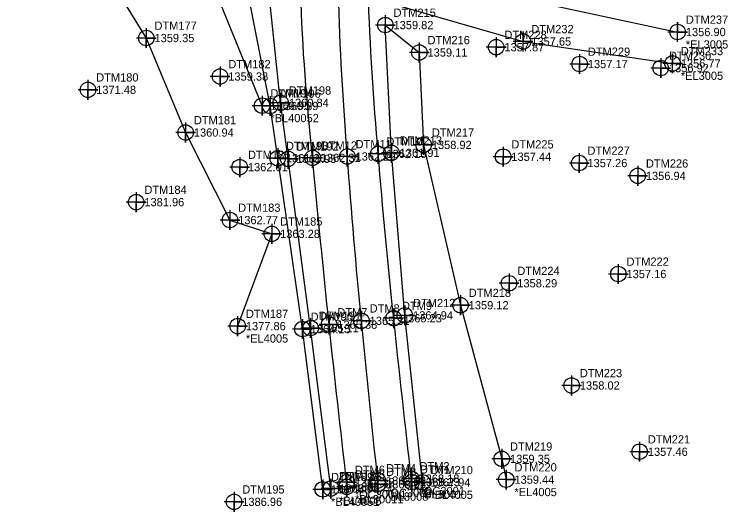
# Model space of a CAD drawing. Extents: x 1251905 to 1252853, y 859795 to 860170.
# Drawn here: x 1251936.6 to 1252152.8, y 859794.9 to 859945.7 of the extents above; entities that cross this region are included whole.
import ezdxf

# ---------------------------------------------------------------- set-up
doc = ezdxf.new("R2010")
doc.units = 0
for name, color, linetype in [('Exist DTM Breakline', 7, 'Continuous'), ('Exist DTM Breakline Cogo Comment', 7, 'Continuous'), ('Exist DTM Breakline Cogo Elevation', 7, 'Continuous'), ('Exist DTM Breakline Cogo Number', 7, 'Continuous'), ('Exist DTM Breakline Cogo Point CELL', 7, 'Continuous'), ('Exist DTM Crownline', 7, 'Continuous'), ('Exist DTM Crownline Cogo Comment', 7, 'Continuous'), ('Exist DTM Crownline Cogo Elevation', 7, 'Continuous'), ('Exist DTM Crownline Cogo Number', 7, 'Continuous'), ('Exist DTM Crownline Cogo Point CELL', 7, 'Continuous'), ('Exist DTM Regular Point CELL', 7, 'Continuous'), ('Exist DTM Regular Point Cogo Elevation', 7, 'Continuous'), ('Exist DTM Regular Point Cogo Number', 7, 'Continuous'), ('Exist Roads EOP', 7, 'Continuous'), ('Exist Roads EOP Cogo Comment', 7, 'Continuous'), ('Exist Roads EOP Cogo Elevation', 7, 'Continuous'), ('Exist Roads EOP Cogo Number', 7, 'Continuous'), ('Exist Roads EOP Cogo Point CELL', 7, 'Continuous'), ('Exist Roads Soil', 7, 'Continuous'), ('Exist Roads Soil Cogo Comment', 7, 'Continuous'), ('Exist Roads Soil Cogo Elevation', 7, 'Continuous'), ('Exist Roads Soil Cogo Number', 7, 'Continuous'), ('Exist Roads Soil Cogo Point CELL', 7, 'Continuous')]:
    doc.layers.add(name, color=color, linetype=linetype)

msp = doc.modelspace()

# ---------------------------------------------------------------- linework, layer by layer
at = {"layer": 'Exist DTM Breakline'}
for points in [[(1251936.565, 859997.923), (1251956.275, 859971.296), (1251976.565, 859938.46), (1251988.5, 859909.824), (1252001.927, 859883.296), (1252014.633, 859879.112), (1252004.267, 859851.158)], [(1252011.684, 859917.958), (1251989.391, 859972.821), (1251996.782, 859981.337), (1252006.454, 859983.238), (1252008.913, 859995.179)], [(1252032.55, 859801.96), (1252026.376, 859850.562), (1252019.584, 859901.847), (1252017.298, 859918.826), (1252013.415, 859955.727), (1252011.851, 859976.908), (1252000.895, 859976.087), (1251994.179, 859971.747), (1252003.085, 859957.255)], [(1252030.055, 859801.697), (1252023.898, 859850.26), (1252016.404, 859902.034), (1252014.144, 859917.861), (1252007.209, 859953.081), (1252007.638, 859960.249), (1252006.494, 859966.213)], [(1252060.248, 859803.803), (1252054.938, 859854.413), (1252050.881, 859903.672), (1252049.022, 859942.38), (1252059.32, 859934.082), (1252060.624, 859906.072), (1252071.802, 859857.487), (1252084.323, 859810.927), (1252085.669, 859804.631)]]:
    msp.add_lwpolyline(points, dxfattribs=at)
at = {"layer": 'Exist DTM Breakline Cogo Point CELL'}
for points in [[(1252049.022, 859945.38), (1252049.022, 859939.38), (1252049.022, 859942.38), (1252052.022, 859942.38), (1252046.022, 859942.38)], [(1251976.565, 859941.46), (1251976.565, 859935.46), (1251976.565, 859938.46), (1251979.565, 859938.46), (1251973.565, 859938.46)], [(1252059.32, 859937.082), (1252059.32, 859931.082), (1252059.32, 859934.082), (1252062.32, 859934.082), (1252056.32, 859934.082)], [(1252011.684, 859920.958), (1252011.684, 859914.958), (1252011.684, 859917.958), (1252014.684, 859917.958), (1252008.684, 859917.958)], [(1252014.144, 859920.861), (1252014.144, 859914.861), (1252014.144, 859917.861), (1252017.144, 859917.861), (1252011.144, 859917.861)], [(1252017.298, 859921.826), (1252017.298, 859915.826), (1252017.298, 859918.826), (1252020.298, 859918.826), (1252014.298, 859918.826)], [(1251988.5, 859912.824), (1251988.5, 859906.824), (1251988.5, 859909.824), (1251991.5, 859909.824), (1251985.5, 859909.824)], [(1252060.624, 859909.072), (1252060.624, 859903.072), (1252060.624, 859906.072), (1252063.624, 859906.072), (1252057.624, 859906.072)], [(1252050.881, 859906.672), (1252050.881, 859900.672), (1252050.881, 859903.672), (1252053.881, 859903.672), (1252047.881, 859903.672)], [(1252016.404, 859905.034), (1252016.404, 859899.034), (1252016.404, 859902.034), (1252019.404, 859902.034), (1252013.404, 859902.034)], [(1252019.584, 859904.847), (1252019.584, 859898.847), (1252019.584, 859901.847), (1252022.584, 859901.847), (1252016.584, 859901.847)], [(1252001.927, 859886.296), (1252001.927, 859880.296), (1252001.927, 859883.296), (1252004.927, 859883.296), (1251998.927, 859883.296)], [(1252014.633, 859882.112), (1252014.633, 859876.112), (1252014.633, 859879.112), (1252017.633, 859879.112), (1252011.633, 859879.112)], [(1252071.802, 859860.487), (1252071.802, 859854.487), (1252071.802, 859857.487), (1252074.802, 859857.487), (1252068.802, 859857.487)], [(1252054.938, 859857.413), (1252054.938, 859851.413), (1252054.938, 859854.413), (1252057.938, 859854.413), (1252051.938, 859854.413)], [(1252004.267, 859854.158), (1252004.267, 859848.158), (1252004.267, 859851.158), (1252007.267, 859851.158), (1252001.267, 859851.158)], [(1252023.898, 859853.26), (1252023.898, 859847.26), (1252023.898, 859850.26), (1252026.898, 859850.26), (1252020.898, 859850.26)], [(1252026.376, 859853.562), (1252026.376, 859847.562), (1252026.376, 859850.562), (1252029.376, 859850.562), (1252023.376, 859850.562)], [(1252084.323, 859813.927), (1252084.323, 859807.927), (1252084.323, 859810.927), (1252087.323, 859810.927), (1252081.323, 859810.927)], [(1252060.248, 859806.803), (1252060.248, 859800.803), (1252060.248, 859803.803), (1252063.248, 859803.803), (1252057.248, 859803.803)], [(1252085.669, 859807.631), (1252085.669, 859801.631), (1252085.669, 859804.631), (1252088.669, 859804.631), (1252082.669, 859804.631)], [(1252030.055, 859804.697), (1252030.055, 859798.697), (1252030.055, 859801.697), (1252033.055, 859801.697), (1252027.055, 859801.697)], [(1252032.55, 859804.96), (1252032.55, 859798.96), (1252032.55, 859801.96), (1252035.55, 859801.96), (1252029.55, 859801.96)]]:
    msp.add_lwpolyline(points, dxfattribs=at)
for centre in [(1252049.022, 859942.38), (1251976.565, 859938.46), (1252059.32, 859934.082), (1252011.684, 859917.958), (1252014.144, 859917.861), (1252017.298, 859918.826), (1251988.5, 859909.824), (1252060.624, 859906.072), (1252050.881, 859903.672), (1252016.404, 859902.034), (1252019.584, 859901.847), (1252001.927, 859883.296), (1252014.633, 859879.112), (1252071.802, 859857.487), (1252054.938, 859854.413), (1252004.267, 859851.158), (1252023.898, 859850.26), (1252026.376, 859850.562), (1252084.323, 859810.927), (1252060.248, 859803.803), (1252085.669, 859804.631), (1252030.055, 859801.697), (1252032.55, 859801.96)]:
    msp.add_circle(centre, 2.344, dxfattribs=at)
at = {"layer": 'Exist DTM Crownline'}
msp.add_line((1252046.759, 859803.242), (1252046.752, 859804.377), dxfattribs=at)
msp.add_spline([(1252046.752, 859804.377), (1252041.79, 859852.778), (1252037.509, 859902.564), (1252034.798, 859952.124), (1252034.696, 859999.877)], degree=3, dxfattribs=at)
at = {"layer": 'Exist DTM Crownline Cogo Point CELL'}
for points in [[(1252037.509, 859905.564), (1252037.509, 859899.564), (1252037.509, 859902.564), (1252040.509, 859902.564), (1252034.509, 859902.564)], [(1252041.79, 859855.778), (1252041.79, 859849.778), (1252041.79, 859852.778), (1252044.79, 859852.778), (1252038.79, 859852.778)], [(1252046.752, 859807.377), (1252046.752, 859801.377), (1252046.752, 859804.377), (1252049.752, 859804.377), (1252043.752, 859804.377)], [(1252046.759, 859806.242), (1252046.759, 859800.242), (1252046.759, 859803.242), (1252049.759, 859803.242), (1252043.759, 859803.242)]]:
    msp.add_lwpolyline(points, dxfattribs=at)
for centre in [(1252037.509, 859902.564), (1252041.79, 859852.778), (1252046.752, 859804.377), (1252046.759, 859803.242)]:
    msp.add_circle(centre, 2.344, dxfattribs=at)
at = {"layer": 'Exist DTM Regular Point CELL'}
for points in [[(1252082.627, 859938.676), (1252082.627, 859932.676), (1252082.627, 859935.676), (1252085.627, 859935.676), (1252079.627, 859935.676)], [(1252107.912, 859933.58), (1252107.912, 859927.58), (1252107.912, 859930.58), (1252110.912, 859930.58), (1252104.912, 859930.58)], [(1252132.491, 859932.353), (1252132.491, 859926.353), (1252132.491, 859929.353), (1252135.491, 859929.353), (1252129.491, 859929.353)], [(1251998.936, 859929.801), (1251998.936, 859923.801), (1251998.936, 859926.801), (1252001.936, 859926.801), (1251995.936, 859926.801)], [(1251958.9, 859925.768), (1251958.9, 859919.768), (1251958.9, 859922.768), (1251961.9, 859922.768), (1251955.9, 859922.768)], [(1252084.728, 859905.485), (1252084.728, 859899.485), (1252084.728, 859902.485), (1252087.728, 859902.485), (1252081.728, 859902.485)], [(1252107.798, 859903.579), (1252107.798, 859897.579), (1252107.798, 859900.579), (1252110.798, 859900.579), (1252104.798, 859900.579)], [(1252004.885, 859902.335), (1252004.885, 859896.335), (1252004.885, 859899.335), (1252007.885, 859899.335), (1252001.885, 859899.335)], [(1252125.509, 859899.69), (1252125.509, 859893.69), (1252125.509, 859896.69), (1252128.509, 859896.69), (1252122.509, 859896.69)], [(1251973.504, 859891.734), (1251973.504, 859885.734), (1251973.504, 859888.734), (1251976.504, 859888.734), (1251970.504, 859888.734)], [(1252119.631, 859869.949), (1252119.631, 859863.949), (1252119.631, 859866.949), (1252122.631, 859866.949), (1252116.631, 859866.949)], [(1252086.531, 859867.149), (1252086.531, 859861.149), (1252086.531, 859864.149), (1252089.531, 859864.149), (1252083.531, 859864.149)], [(1252105.494, 859836.174), (1252105.494, 859830.174), (1252105.494, 859833.174), (1252108.494, 859833.174), (1252102.494, 859833.174)], [(1252126.096, 859816.089), (1252126.096, 859810.089), (1252126.096, 859813.089), (1252129.096, 859813.089), (1252123.096, 859813.089)], [(1252003.171, 859800.911), (1252003.171, 859794.911), (1252003.171, 859797.911), (1252006.171, 859797.911), (1252000.171, 859797.911)]]:
    msp.add_lwpolyline(points, dxfattribs=at)
for centre in [(1252082.627, 859935.676), (1252107.912, 859930.58), (1252132.491, 859929.353), (1251998.936, 859926.801), (1251958.9, 859922.768), (1252084.728, 859902.485), (1252107.798, 859900.579), (1252004.885, 859899.335), (1252125.509, 859896.69), (1251973.504, 859888.734), (1252119.631, 859866.949), (1252086.531, 859864.149), (1252105.494, 859833.174), (1252126.096, 859813.089), (1252003.171, 859797.911)]:
    msp.add_circle(centre, 2.344, dxfattribs=at)
at = {"layer": 'Exist Roads EOP'}
for p, q in [((1252037.345, 859802.459), (1252037.3, 859803.862)), ((1252057.02, 859803.94), (1252056.897, 859804.944))]:
    msp.add_line(p, q, dxfattribs=at)
for points in [[(1252037.3, 859803.862), (1252031.99, 859851.603), (1252026.974, 859902.147), (1252023.461, 859952.269), (1252025.019, 859999.306)], [(1252056.897, 859804.944), (1252051.57, 859853.552), (1252046.862, 859903.357), (1252043.821, 859952.535), (1252043.399, 859998.083)]]:
    msp.add_spline(points, degree=3, dxfattribs=at)
at = {"layer": 'Exist Roads EOP Cogo Point CELL'}
for points in [[(1252026.974, 859905.147), (1252026.974, 859899.147), (1252026.974, 859902.147), (1252029.974, 859902.147), (1252023.974, 859902.147)], [(1252046.862, 859906.357), (1252046.862, 859900.357), (1252046.862, 859903.357), (1252049.862, 859903.357), (1252043.862, 859903.357)], [(1252051.57, 859856.552), (1252051.57, 859850.552), (1252051.57, 859853.552), (1252054.57, 859853.552), (1252048.57, 859853.552)], [(1252031.99, 859854.603), (1252031.99, 859848.603), (1252031.99, 859851.603), (1252034.99, 859851.603), (1252028.99, 859851.603)], [(1252056.897, 859807.944), (1252056.897, 859801.944), (1252056.897, 859804.944), (1252059.897, 859804.944), (1252053.897, 859804.944)], [(1252037.3, 859806.862), (1252037.3, 859800.862), (1252037.3, 859803.862), (1252040.3, 859803.862), (1252034.3, 859803.862)], [(1252057.02, 859806.94), (1252057.02, 859800.94), (1252057.02, 859803.94), (1252060.02, 859803.94), (1252054.02, 859803.94)], [(1252037.345, 859805.459), (1252037.345, 859799.459), (1252037.345, 859802.459), (1252040.345, 859802.459), (1252034.345, 859802.459)]]:
    msp.add_lwpolyline(points, dxfattribs=at)
for centre in [(1252046.862, 859903.357), (1252026.974, 859902.147), (1252051.57, 859853.552), (1252031.99, 859851.603), (1252037.3, 859803.862), (1252056.897, 859804.944), (1252057.02, 859803.94), (1252037.345, 859802.459)]:
    msp.add_circle(centre, 2.344, dxfattribs=at)
at = {"layer": 'Exist Roads Soil'}
for points in [[(1252044.791, 859969.904), (1252064.824, 859958.222), (1252092.402, 859950.074), (1252137.619, 859940.278)], [(1252044.096, 859950.97), (1252090.774, 859937.412), (1252136.088, 859930.761)]]:
    msp.add_lwpolyline(points, dxfattribs=at)
at = {"layer": 'Exist Roads Soil Cogo Point CELL'}
for points in [[(1252137.619, 859937.278), (1252137.619, 859943.278), (1252137.619, 859940.278), (1252140.619, 859940.278), (1252134.619, 859940.278)], [(1252090.774, 859934.412), (1252090.774, 859940.412), (1252090.774, 859937.412), (1252093.774, 859937.412), (1252087.774, 859937.412)], [(1252136.088, 859927.761), (1252136.088, 859933.761), (1252136.088, 859930.761), (1252139.088, 859930.761), (1252133.088, 859930.761)]]:
    msp.add_lwpolyline(points, dxfattribs=at)
for centre in [(1252137.619, 859940.278), (1252090.774, 859937.412), (1252136.088, 859930.761)]:
    msp.add_circle(centre, 2.344, dxfattribs=at)

# ---------------------------------------------------------------- texts
at = {"layer": 'Exist DTM Breakline Cogo Comment'}
for s, p in [('*BL40052', (1252014.184, 859912.958)), ('*EL4005', (1252006.767, 859846.158)), ('*BL4005', (1252062.748, 859798.803)), ('*EL4005', (1252088.169, 859799.631)), ('*BL40051', (1252032.555, 859796.697)), ('*BL4005', (1252035.05, 859796.96))]:
    msp.add_text(s, height=2.5, dxfattribs=at).set_placement(p)
at = {"layer": 'Exist DTM Breakline Cogo Elevation'}
for s, p in [('1359.82', (1252051.522, 859941.13)), ('1359.35', (1251979.065, 859937.21)), ('1359.11', (1252061.82, 859932.832)), ('1360.95', (1252014.184, 859916.708)), ('1360.39', (1252016.644, 859916.611)), ('1360.84', (1252019.798, 859917.576)), ('1360.94', (1251991, 859908.574)), ('1358.92', (1252063.124, 859904.822)), ('1361.20', (1252018.904, 859900.784)), ('1361.95', (1252022.084, 859900.597)), ('1361.91', (1252053.381, 859902.422)), ('1362.77', (1252004.427, 859882.046)), ('1363.28', (1252017.133, 859877.862)), ('1359.12', (1252074.302, 859856.237)), ('1364.94', (1252057.438, 859853.163)), ('1377.86', (1252006.767, 859849.908)), ('1364.15', (1252026.398, 859849.01)), ('1365.11', (1252028.876, 859849.312)), ('1359.35', (1252086.823, 859809.677)), ('1359.44', (1252088.169, 859803.381)), ('1367.94', (1252062.748, 859802.553)), ('1367.40', (1252032.555, 859800.447)), ('1368.09', (1252035.05, 859800.71))]:
    msp.add_text(s, height=2.5, dxfattribs=at).set_placement(p)
at = {"layer": 'Exist DTM Breakline Cogo Number'}
for s, p in [('DTM215', (1252051.522, 859944.88)), ('DTM177', (1251979.065, 859940.96)), ('DTM216', (1252061.82, 859936.582)), ('DTM194', (1252014.184, 859920.458)), ('DTM196', (1252016.644, 859920.361)), ('DTM198', (1252019.798, 859921.326)), ('DTM181', (1251991, 859912.324)), ('DTM217', (1252063.124, 859908.572)), ('DTM213', (1252053.381, 859906.172)), ('DTM193', (1252018.904, 859904.534)), ('DTM192', (1252022.084, 859904.347)), ('DTM183', (1252004.427, 859885.796)), ('DTM185', (1252017.133, 859881.612)), ('DTM218', (1252074.302, 859859.987)), ('DTM212', (1252057.438, 859856.913)), ('DTM187', (1252006.767, 859853.658)), ('DTM191', (1252028.876, 859853.062)), ('DTM190', (1252026.398, 859852.76)), ('DTM219', (1252086.823, 859813.427)), ('DTM210', (1252062.748, 859806.303)), ('DTM220', (1252088.169, 859807.131)), ('DTM189', (1252032.555, 859804.197)), ('DTM188', (1252035.05, 859804.46))]:
    msp.add_text(s, height=2.5, dxfattribs=at).set_placement(p)
at = {"layer": 'Exist DTM Crownline Cogo Comment'}
for s, p in [('*OC3008', (1252049.252, 859799.377)), ('*BL3008', (1252049.259, 859798.242))]:
    msp.add_text(s, height=2.5, dxfattribs=at).set_placement(p)
at = {"layer": 'Exist DTM Crownline Cogo Elevation'}
for s, p in [('1362.29', (1252040.009, 859901.314)), ('1365.31', (1252044.29, 859851.528)), ('1368.19', (1252049.252, 859803.127)), ('1368.25', (1252049.259, 859801.992))]:
    msp.add_text(s, height=2.5, dxfattribs=at).set_placement(p)
at = {"layer": 'Exist DTM Crownline Cogo Number'}
for s, p in [('DTM11', (1252040.009, 859905.064)), ('DTM8', (1252044.29, 859855.278)), ('DTM4', (1252049.252, 859806.877)), ('DTM3', (1252049.259, 859805.742))]:
    msp.add_text(s, height=2.5, dxfattribs=at).set_placement(p)
at = {"layer": 'Exist DTM Regular Point Cogo Elevation'}
for s, p in [('1357.87', (1252085.127, 859934.426)), ('1357.17', (1252110.412, 859929.33)), ('1356.92', (1252134.991, 859928.103)), ('1359.38', (1252001.436, 859925.551)), ('1371.48', (1251961.4, 859921.518)), ('1357.44', (1252087.228, 859901.235)), ('1357.26', (1252110.298, 859899.329)), ('1362.01', (1252007.385, 859898.085)), ('1356.94', (1252128.009, 859895.44)), ('1381.96', (1251976.004, 859887.484)), ('1357.16', (1252122.131, 859865.699)), ('1358.29', (1252089.031, 859862.899)), ('1358.02', (1252107.994, 859831.924)), ('1357.46', (1252128.596, 859811.839)), ('1386.96', (1252005.671, 859796.661))]:
    msp.add_text(s, height=2.5, dxfattribs=at).set_placement(p)
at = {"layer": 'Exist DTM Regular Point Cogo Number'}
for s, p in [('DTM228', (1252085.127, 859938.176)), ('DTM229', (1252110.412, 859933.08)), ('DTM230', (1252134.991, 859931.853)), ('DTM182', (1252001.436, 859929.301)), ('DTM180', (1251961.4, 859925.268)), ('DTM225', (1252087.228, 859904.985)), ('DTM227', (1252110.298, 859903.079)), ('DTM186', (1252007.385, 859901.835)), ('DTM226', (1252128.009, 859899.19)), ('DTM184', (1251976.004, 859891.234)), ('DTM222', (1252122.131, 859869.449)), ('DTM224', (1252089.031, 859866.649)), ('DTM223', (1252107.994, 859835.674)), ('DTM221', (1252128.596, 859815.589)), ('DTM195', (1252005.671, 859800.411))]:
    msp.add_text(s, height=2.5, dxfattribs=at).set_placement(p)
at = {"layer": 'Exist Roads EOP Cogo Comment'}
for s, p in [('*OC30011', (1252039.8, 859798.862)), ('*OC3001', (1252059.397, 859799.944)), ('*BL3001', (1252059.52, 859798.94)), ('*BL30011', (1252039.845, 859797.459))]:
    msp.add_text(s, height=2.5, dxfattribs=at).set_placement(p)
at = {"layer": 'Exist Roads EOP Cogo Elevation'}
for s, p in [('1362.31', (1252029.474, 859900.897)), ('1362.16', (1252049.362, 859902.107)), ('1365.23', (1252054.07, 859852.302)), ('1365.38', (1252034.49, 859850.353)), ('1368.18', (1252059.397, 859803.694)), ('1368.18', (1252039.8, 859802.612)), ('1368.26', (1252039.845, 859801.209)), ('1368.23', (1252059.52, 859802.69))]:
    msp.add_text(s, height=2.5, dxfattribs=at).set_placement(p)
at = {"layer": 'Exist Roads EOP Cogo Number'}
for s, p in [('DTM10', (1252049.362, 859905.857)), ('DTM12', (1252029.474, 859904.647)), ('DTM9', (1252054.07, 859856.052)), ('DTM7', (1252034.49, 859854.103)), ('DTM2', (1252059.397, 859807.444)), ('DTM6', (1252039.8, 859806.362)), ('DTM1', (1252059.52, 859806.44)), ('DTM5', (1252039.845, 859804.959))]:
    msp.add_text(s, height=2.5, dxfattribs=at).set_placement(p)
at = {"layer": 'Exist Roads Soil Cogo Comment'}
for p in [(1252140.119, 859935.278), (1252138.588, 859925.761)]:
    msp.add_text('*EL3005', height=2.5, dxfattribs=at).set_placement(p)
at = {"layer": 'Exist Roads Soil Cogo Elevation'}
for s, p in [('1356.90', (1252140.119, 859939.028)), ('1357.65', (1252093.274, 859936.162)), ('1356.77', (1252138.588, 859929.511))]:
    msp.add_text(s, height=2.5, dxfattribs=at).set_placement(p)
at = {"layer": 'Exist Roads Soil Cogo Number'}
for s, p in [('DTM237', (1252140.119, 859942.778)), ('DTM232', (1252093.274, 859939.912)), ('DTM233', (1252138.588, 859933.261))]:
    msp.add_text(s, height=2.5, dxfattribs=at).set_placement(p)

doc.saveas('drawing.dxf')
